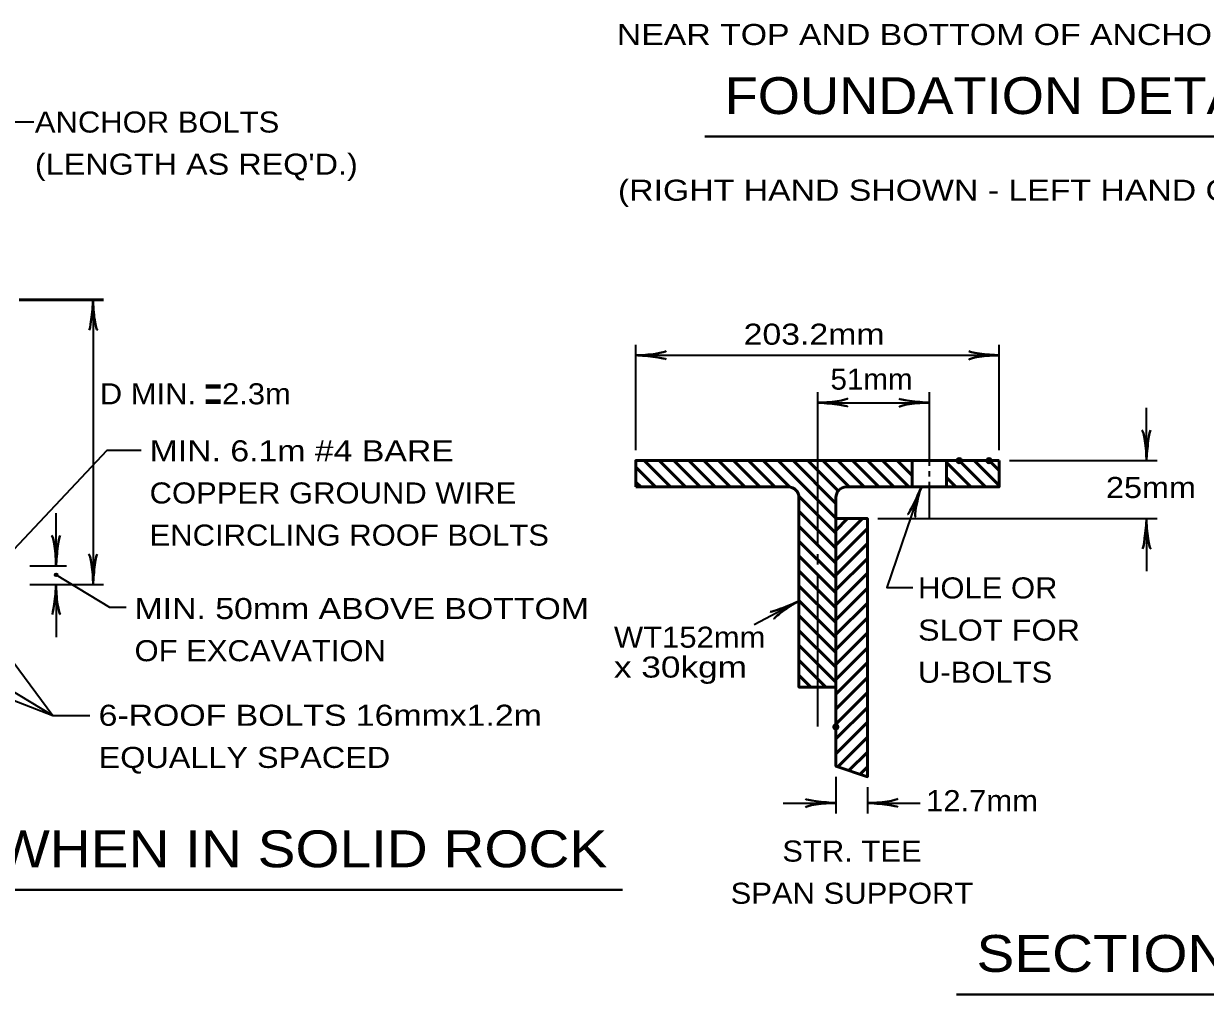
# Model space of a CAD drawing. Extents: x -35 to 821, y -13 to 531.
# Drawn here: x 455.8 to 590.5, y 143.6 to 254.2 of the extents above; entities that cross this region are included whole.
import ezdxf
from ezdxf.enums import TextEntityAlignment as Align

# ---------------------------------------------------------------- set-up
doc = ezdxf.new("R2010")
doc.units = 0
doc.header["$LTSCALE"] = 0.96
doc.header["$PDMODE"] = 32
doc.header["$PDSIZE"] = 0.48
doc.layers.add('1', color=7, linetype='Continuous', lineweight=53)

msp = doc.modelspace()

# ---------------------------------------------------------------- hatches: boundary and pattern name
at = {"layer": '1'}
msp.add_hatch(color=256, dxfattribs=at).paths.add_polyline_path([(459.7106, 191.4078, 1), (459.399, 191.4078, 1)])

# ---------------------------------------------------------------- linework, layer by layer
at = {"layer": '1', "lineweight": 40}
for p, q in [((533.4496, 241.3446), (600.7062, 241.3446)), ((385.8624, 155.5485), (524.0727, 155.5485)), ((562.1502, 143.6344), (608.4321, 143.6344))]:
    msp.add_line(p, q, dxfattribs=at)
at = {"layer": '1'}
for p, q in [((455.3334, 222.7358), (464.9547, 222.7358)), ((566.9943, 204.4293), (525.5943, 204.4293)), ((527.8521, 201.4293), (525.5943, 203.6871)), ((529.5492, 201.4293), (526.5492, 204.4293)), ((531.2462, 201.4293), (528.2462, 204.4293)), ((532.9433, 201.4293), (529.9433, 204.4293)), ((534.6403, 201.4293), (531.6403, 204.4293)), ((536.3374, 201.4293), (533.3374, 204.4293)), ((538.0345, 201.4293), (535.0345, 204.4293)), ((539.7315, 201.4293), (536.7315, 204.4293)), ((541.4286, 201.4293), (538.4286, 204.4293)), ((543.1345, 201.4204), (540.1256, 204.4293)), ((548.3943, 197.8577), (541.8227, 204.4293)), ((548.3943, 199.5547), (543.5197, 204.4293)), ((548.6628, 200.9833), (545.2168, 204.4293)), ((549.9139, 201.4293), (546.9139, 204.4293)), ((551.6109, 201.4293), (548.6109, 204.4293)), ((553.308, 201.4293), (550.308, 204.4293)), ((555.005, 201.4293), (552.005, 204.4293)), ((556.7021, 201.4293), (553.7021, 204.4293)), ((557.0943, 202.7341), (555.3991, 204.4293)), ((560.9943, 201.4293), (560.9943, 204.4293)), ((563.7618, 201.4293), (560.9943, 204.1968)), ((565.4589, 201.4293), (562.4589, 204.4293)), ((566.9943, 201.591), (564.156, 204.4293)), ((566.9943, 203.288), (565.853, 204.4293)), ((562.0648, 201.4293), (560.9943, 202.4998)), ((526.1551, 201.4293), (525.5943, 201.9901)), ((542.9943, 201.4293), (525.5943, 201.4293)), ((557.0943, 201.4293), (560.9943, 201.4293)), ((548.3943, 196.1606), (544.1854, 200.3695)), ((548.3943, 200.2293), (548.3943, 169.6293)), ((548.3943, 194.4636), (544.1943, 198.6636)), ((548.3943, 192.7665), (544.1943, 196.9665)), ((548.3943, 196.4857), (549.7379, 197.8293)), ((548.3943, 194.7886), (551.435, 197.8293)), ((548.3943, 193.0915), (551.9943, 196.6915)), ((548.3943, 191.0695), (544.1943, 195.2695)), ((548.3943, 191.3945), (551.9943, 194.9945)), ((548.3943, 189.3724), (544.1943, 193.5724)), ((548.3943, 189.6974), (551.9943, 193.2974)), ((548.3943, 187.6753), (544.1943, 191.8753)), ((548.3943, 188.0004), (551.9943, 191.6004)), ((548.3943, 185.9783), (544.1943, 190.1783)), ((548.3943, 186.3033), (551.9943, 189.9033)), ((548.3943, 184.2812), (544.1943, 188.4812)), ((548.3943, 184.6063), (551.9943, 188.2063)), ((548.3943, 182.5842), (544.1943, 186.7842)), ((548.3943, 182.9092), (551.9943, 186.5092)), ((548.3943, 180.8871), (544.1943, 185.0871)), ((548.3943, 181.2122), (551.9943, 184.8122)), ((548.3943, 179.1901), (544.1943, 183.3901)), ((548.3943, 179.5151), (551.9943, 183.1151)), ((547.258, 178.6293), (544.1943, 181.693)), ((548.3943, 177.818), (551.9943, 181.418)), ((545.5609, 178.6293), (544.1943, 179.9959)), ((548.3943, 176.121), (551.9943, 179.721)), ((548.3943, 174.4239), (551.9943, 178.0239)), ((548.3943, 172.7269), (551.9943, 176.3269)), ((548.3943, 171.0298), (551.9943, 174.6298)), ((548.6167, 169.5552), (551.9943, 172.9328)), ((549.8895, 169.1309), (551.9943, 171.2357)), ((551.1623, 168.7066), (551.9943, 169.5386))]:
    msp.add_line(p, q, dxfattribs=at)
at = {"layer": '1', "lineweight": 35}
for p, q in [((463.7547, 222.7358), (463.7547, 190.3357)), ((525.5943, 205.6293), (525.5943, 217.6293)), ((566.9943, 205.6293), (566.9943, 217.6293)), ((525.5943, 216.4293), (566.9943, 216.4293)), ((546.2943, 212.2293), (546.2943, 194.9793)), ((559.0443, 212.2293), (559.0443, 203.8293)), ((546.2943, 211.0293), (559.0443, 211.0293)), ((583.7943, 204.4293), (583.7943, 210.4293)), ((568.1943, 204.4293), (584.9943, 204.4293)), ((559.0443, 203.2293), (559.0443, 202.6293)), ((559.0443, 202.0293), (559.0443, 197.8293)), ((459.5334, 192.4357), (459.5334, 198.4357)), ((553.1943, 197.8293), (584.9943, 197.8293)), ((583.7943, 197.8293), (583.7943, 191.8293)), ((546.2943, 193.7793), (546.2943, 192.5793)), ((456.5334, 192.4357), (460.7334, 192.4357)), ((546.2943, 191.3793), (546.2943, 174.1293)), ((456.5334, 190.3357), (464.9547, 190.3357)), ((459.5334, 190.3357), (459.5334, 184.3357)), ((544.1943, 188.4337), (539.0917, 185.7315)), ((433.8834, 185.2357), (459.1446, 175.3797)), ((442.8834, 185.2357), (459.1446, 175.3797)), ((451.8834, 185.2357), (459.1446, 175.3797)), ((459.1446, 175.3797), (463.3939, 175.3797)), ((548.3943, 168.4293), (548.3943, 164.2293)), ((551.9943, 167.2293), (551.9943, 164.2293)), ((542.3943, 165.4293), (548.3943, 165.4293)), ((551.9943, 165.4293), (557.9943, 165.4293))]:
    msp.add_line(p, q, dxfattribs=at)
for points in [[(446.3334, 227.5357), (451.256, 243.0208), (456.9977, 243.0019)], [(452.9334, 192.4357), (465.3716, 205.6121), (469.2367, 205.6121)], [(558.1305, 201.4293), (554.2029, 189.9701), (557.1794, 189.9701)], [(459.5548, 191.4078), (465.6311, 187.7239), (467.5338, 187.7239)]]:
    msp.add_lwpolyline(points, dxfattribs=at)
at = {"layer": '1'}
for points in [[(525.5943, 201.4293), (525.5943, 204.4293), (566.9943, 204.4293)], [(557.0943, 204.4293), (557.0943, 201.4293), (549.5943, 201.4293)], [(566.9943, 204.4293), (566.9943, 201.4293), (560.9943, 201.4293)], [(548.3943, 178.6293), (544.1943, 178.6293), (544.1943, 200.2293)]]:
    msp.add_lwpolyline(points, dxfattribs=at)
msp.add_lwpolyline([(548.3943, 197.8293), (551.9943, 197.8293), (551.9943, 168.4293), (548.3943, 169.6293), (548.3943, 200.2293)], close=True, dxfattribs=at)
at = {"layer": '1', "lineweight": 35}
msp.add_circle((459.5548, 191.4078), 0.1558, dxfattribs=at)
at = {"layer": '1'}
for centre, start, end in [((542.9943, 200.2293), 0, 90), ((549.5943, 200.2293), 90, 180)]:
    msp.add_arc(centre, 1.2, start, end, dxfattribs=at)
at = {"layer": '1', "lineweight": 40}
for centre, major_axis, ratio, start_param, end_param in [((463.5008, 221.3912), (0.2108, 2.1077), 0.07063, 3.14071475, 5.41810995), ((463.5008, 221.3912), (0.2108, 2.1077), 0.07063, 3.14071475, 5.41810995), ((464.0863, 221.4264), (-0.1874, 2.1428), 0.122415, 0.89635335, 3.14159265), ((464.0863, 221.4264), (-0.1874, 2.1428), 0.122415, 0.89635335, 3.14159265), ((526.9037, 216.7609), (-2.1428, -0.1874), 0.122415, 0.89635335, 3.14159265), ((526.9037, 216.7609), (-2.1428, -0.1874), 0.122415, 0.89635335, 3.14159265), ((565.6497, 216.6832), (2.1077, -0.2108), 0.07063, 3.14071475, 5.41810995), ((526.9389, 216.1754), (-2.1077, 0.2108), 0.07063, 3.14071475, 5.41810995), ((526.9389, 216.1754), (-2.1077, 0.2108), 0.07063, 3.14071475, 5.41810995), ((565.6849, 216.0977), (2.1428, 0.1874), 0.122415, 0.89635335, 3.14159265), ((547.6037, 211.3609), (-2.1428, -0.1874), 0.122415, 0.89635335, 3.14159265), ((547.6037, 211.3609), (-2.1428, -0.1874), 0.122415, 0.89635335, 3.14159265), ((557.6997, 211.2832), (2.1077, -0.2108), 0.07063, 3.14071475, 5.41810995), ((547.6389, 210.7754), (-2.1077, 0.2108), 0.07063, 3.14071475, 5.41810995), ((547.6389, 210.7754), (-2.1077, 0.2108), 0.07063, 3.14071475, 5.41810995), ((557.7349, 210.6977), (2.1428, 0.1874), 0.122415, 0.89635335, 3.14159265), ((583.4627, 205.7387), (0.1874, -2.1428), 0.122415, 0.89635335, 3.14159265), ((584.0482, 205.7739), (-0.2108, -2.1077), 0.07063, 3.14071475, 5.41810995), ((557.4543, 200.2397), (-0.8828, -1.9255), 0.07063, 6.28230741, 8.55970261), ((558.0196, 200.0831), (0.5175, 2.0878), 0.122415, 0.89635335, 3.14159265), ((583.5404, 196.4847), (0.2108, 2.1077), 0.07063, 3.14071475, 5.41810995), ((584.1259, 196.5199), (-0.1874, 2.1428), 0.122415, 0.89635335, 3.14159265), ((459.2018, 193.7451), (0.1874, -2.1428), 0.122415, 0.89635335, 3.14159265), ((459.2018, 193.7451), (0.1874, -2.1428), 0.122415, 0.89635335, 3.14159265), ((459.7873, 193.7803), (-0.2108, -2.1077), 0.07063, 3.14071475, 5.41810995), ((459.7873, 193.7803), (-0.2108, -2.1077), 0.07063, 3.14071475, 5.41810995), ((463.4231, 191.6451), (0.1874, -2.1428), 0.122415, 0.89635335, 3.14159265), ((464.0086, 191.6803), (-0.2108, -2.1077), 0.07063, 3.14071475, 5.41810995), ((459.2795, 188.9911), (0.2108, 2.1077), 0.07063, 3.14071475, 5.41810995), ((459.865, 189.0263), (-0.1874, 2.1428), 0.122415, 0.89635335, 3.14159265), ((542.8872, 188.0288), (-1.9613, -0.8001), 0.07063, 6.28230741, 8.55970261), ((543.1923, 187.5279), (1.806, 1.1684), 0.122415, 0.89635335, 3.14159265), ((547.0497, 165.6832), (2.1077, -0.2108), 0.07063, 3.14071475, 5.41810995), ((547.0497, 165.6832), (2.1077, -0.2108), 0.07063, 3.14071475, 5.41810995), ((553.3037, 165.7609), (-2.1428, -0.1874), 0.122415, 0.89635335, 3.14159265), ((547.0849, 165.0977), (2.1428, 0.1874), 0.122415, 0.89635335, 3.14159265), ((547.0849, 165.0977), (2.1428, 0.1874), 0.122415, 0.89635335, 3.14159265), ((553.3389, 165.1754), (-2.1077, 0.2108), 0.07063, 3.14071475, 5.41810995)]:
    msp.add_ellipse(centre, major_axis=major_axis, ratio=ratio, start_param=start_param, end_param=end_param, dxfattribs=at)
at = {"layer": '1'}
for p in [(562.4589, 204.4293), (565.853, 204.4293), (548.3943, 174.0989)]:
    msp.add_point(p, dxfattribs=at)

# ---------------------------------------------------------------- texts
for s, height, width, p in [('NEAR TOP AND BOTTOM OF ANCHOR BOLTS.', 2.4, 1.2, (523.4368, 251.7679)), ('FOUNDATION DETAIL', 4.2, 1.1, (535.7255, 243.9058)), ('ANCHOR BOLTS', 2.4, 1.1, (457.118, 241.7963)), ("(LENGTH AS REQ'D.)", 2.4, 1.15, (457.118, 236.9963)), ('(RIGHT HAND SHOWN - LEFT HAND OPPOSITE)', 2.4, 1.2, (523.5608, 234.0302)), ('203.2mm', 2.4, 1.2, (537.8867, 217.6305)), ('51mm', 2.4, 1.05, (547.7823, 212.5149)), ('D MIN.   2.3m', 2.4, 1.1, (464.5133, 210.8402)), ('=', 4.8, 0.55, (476.3977, 209.7177)), ('MIN. 6.1m #4 BARE', 2.4, 1.2, (470.192, 204.345)), ('25mm', 2.4, 1.15, (579.1761, 200.1673)), ('COPPER GROUND WIRE', 2.4, 1.1, (470.192, 199.545)), ('ENCIRCLING ROOF BOLTS', 2.4, 1.1, (470.192, 194.745)), ('HOLE OR', 2.4, 1.1, (557.7581, 188.728)), ('MIN. 50mm ABOVE BOTTOM', 2.4, 1.2, (468.4752, 186.3789)), ('SLOT FOR', 2.4, 1.15, (557.7581, 183.928)), ('WT152mm', 2.4, 1.1, (523.106, 183.1163)), ('OF EXCAVATION', 2.4, 1.1, (468.4752, 181.5789)), ('x 30kgm', 2.4, 1.25, (523.106, 179.7163)), ('U-BOLTS', 2.4, 1.1, (557.7581, 179.128)), ('6-ROOF BOLTS 16mmx1.2m', 2.4, 1.2, (464.3813, 174.2254)), ('EQUALLY SPACED', 2.4, 1.15, (464.3813, 169.4254)), ('12.7mm', 2.4, 1.1, (558.6796, 164.4966)), ('MODIFIED FOOTING WHEN IN SOLID ROCK', 4.2, 1.15, (388.1383, 158.1097)), ('SECTION A-A', 4.2, 1.15, (564.4261, 146.1956))]:
    msp.add_text(s, height=height, dxfattribs=dict(at, width=width)).set_placement(p)
at = {"layer": '1', "width": 1.1}
for s, p in [('STR. TEE', (550.2344, 158.7493)), ('SPAN SUPPORT', (550.2342, 153.9493))]:
    msp.add_text(s, height=2.4, dxfattribs=at).set_placement(p, align=Align.CENTER)

doc.saveas('drawing.dxf')
